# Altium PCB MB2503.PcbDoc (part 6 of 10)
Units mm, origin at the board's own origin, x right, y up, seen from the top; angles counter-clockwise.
Board outline 127 x 97 mm, 6 copper layers (Top Layer, Signal Layer 1, Signal Layer 2, Signal Layer 3, Signal Layer 4, Bottom Layer), stack 1.557 mm thick; 572 components, 468 nets, 2377 pads, 1704 vias.
Unrouted connection lines stored in the file: 3.
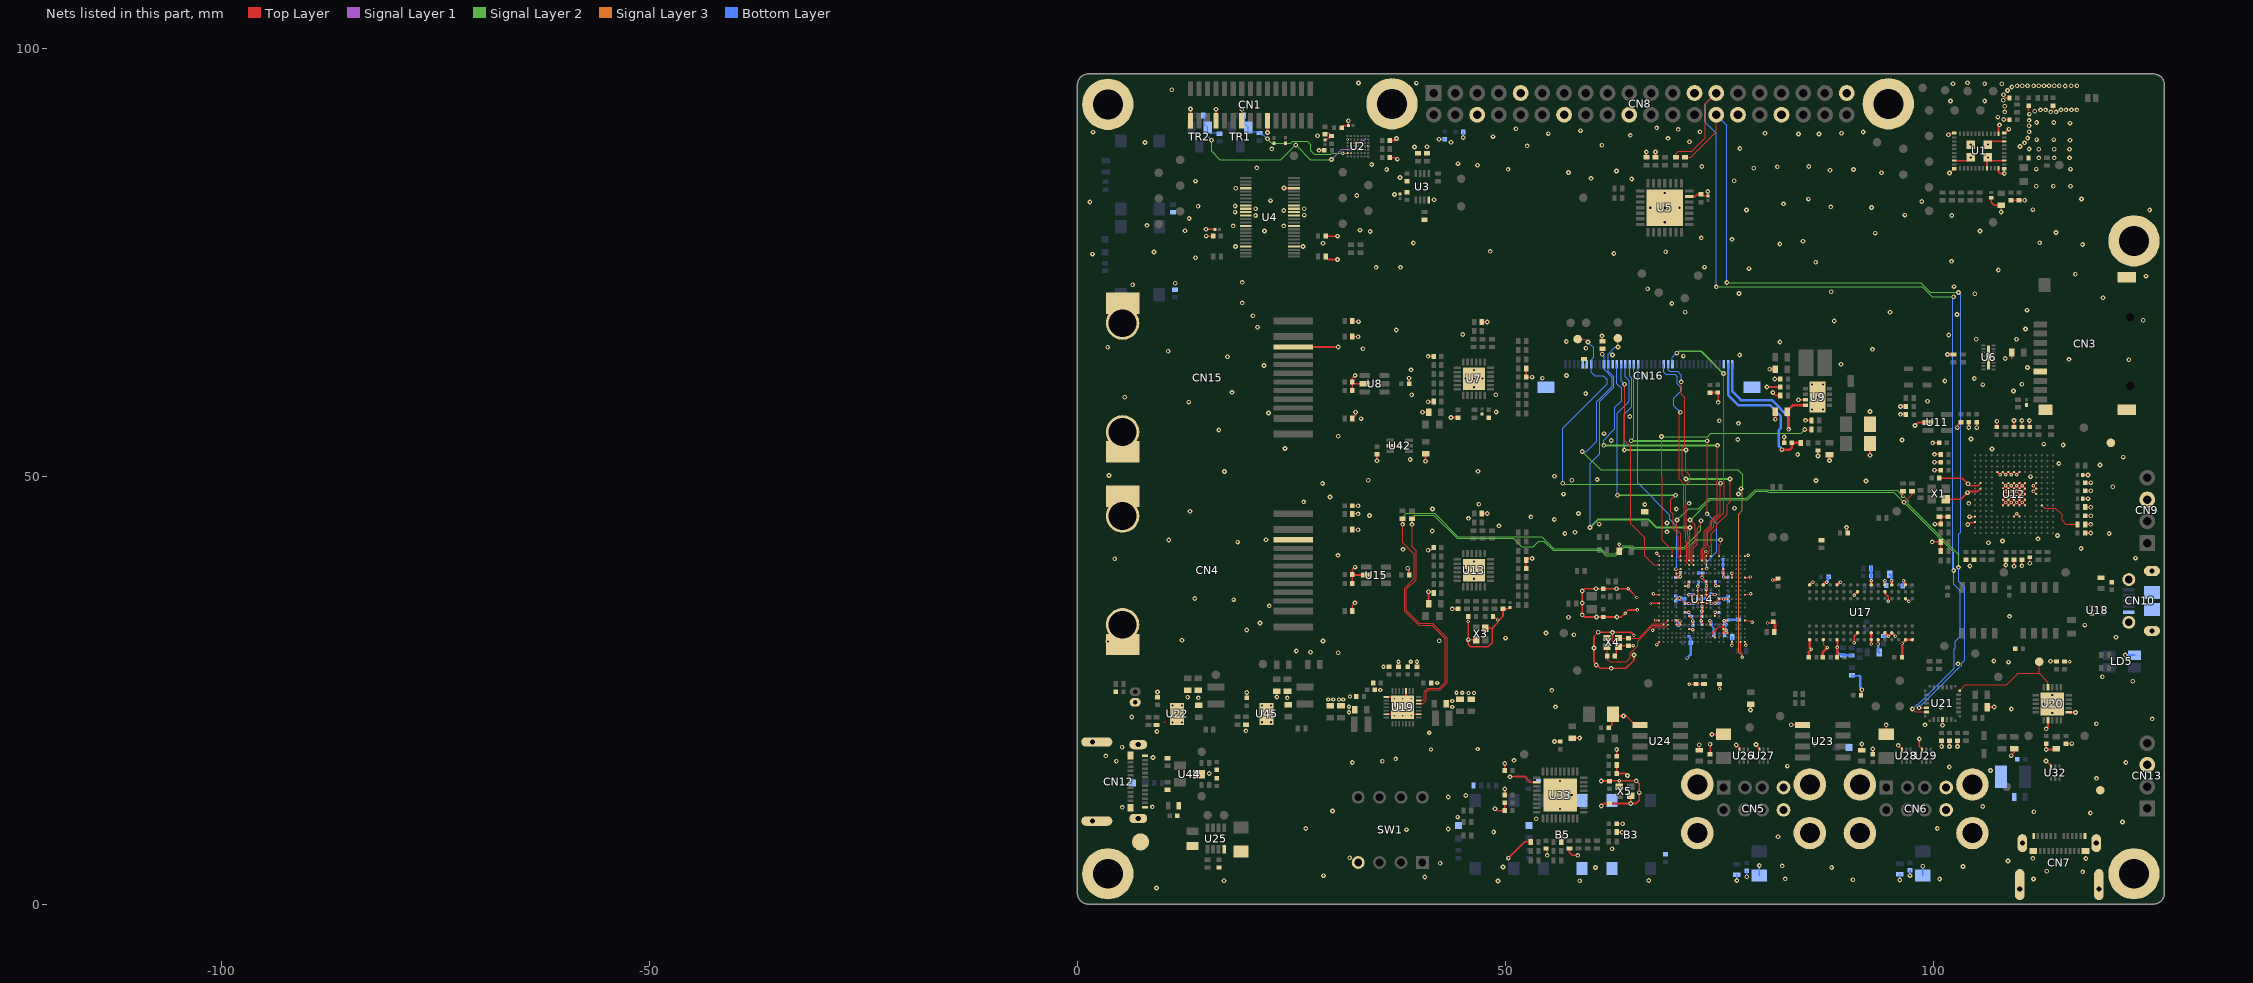
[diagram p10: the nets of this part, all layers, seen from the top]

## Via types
v1: diameter 0.55, hole 0.25, Top Layer to Bottom Layer, 1335 vias
v2: diameter 0.4, hole 0.2, Top Layer to Bottom Layer, 262 vias
v3: diameter 0.5, hole 0.2, Top Layer to Bottom Layer, 51 vias
v4: diameter 0.26, hole 0.1, Top Layer to Signal Layer 1, tented both sides, 29 vias
v5: diameter 0.5, hole 0.25, Top Layer to Bottom Layer, 18 vias
v6: diameter 0.4, hole 0.2, Top Layer to Bottom Layer, tented both sides, 9 vias

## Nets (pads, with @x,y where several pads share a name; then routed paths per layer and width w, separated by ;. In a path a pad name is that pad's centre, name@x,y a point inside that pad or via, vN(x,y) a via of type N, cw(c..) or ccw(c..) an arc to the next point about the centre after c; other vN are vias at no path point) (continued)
GND: B3.1 B3.2 B5.3 B5.4 C1.1 C2.1 C3.1 C4.1 C5.1 C6.1 C7.2 C8.1 C9.1 C10.1 C11.1 C12.1 C13.1 C14.1 C15.1 C16.1 C17.1 C18.1 C19.1 C20.1 C21.1 C22.1 C23.1 C24.1 C25.1 C26.1 C27.1 C28.1 C29.2 C30.1 C31.1 C32.1 C33.2 C34.1 C35.1 C36.2 C37.1 C38.1 C39.2 C40.1 C41.1 C42.1 C43.1 C44.1 C45.1 C46.1 C47.1 C48.1 C49.1 C50.2 C51.1 C52.1 C53.1 C54.1 C55.1 C56.1 C57.1 C58.1 C59.1 C60.1 C61.1 C62.1 C63.1 C64.1 C65.1 C66.1 C67.1 C68.1 C69.1 C70.1 C71.1 C72.1 C73.1 C74.1 C75.1 C76.1 C77.1 C78.1 C79.1 C80.1 C81.2 C82.1 C83.1 C84.1 C85.1 C88.2 C89.1 C90.1 C91.2 C92.1 C93.2 C94.1 C95.1 C96.1 C97.1 C98.1 C99.1 C100.1 C101.1 C102.1 C103.2 C104.1 C105.1 C106.1 C107.2 C108.1 C109.1 C110.1 C111.1 C112.1 C113.1 C114.1 C115.1 C116.1 C117.1 C118.2 C119.1 C120.1 C121.1 C122.1 C123.1 C124.1 C125.1 C126.1 C127.1 C128.1 C129.1 C130.1 C131.1 C133.1 C134.1 C135.1 C136.1 C137.1 C138.1 C139.1 C140.1 C142.1 C144.1 C147.1 C148.1 C149.1 C150.1 C151.2 C152.1 C153.1 C154.1 C155.1 C156.1 C157.1 C158.1 C159.1 C160.1 C161.1 C162.2 C163.1 C164.1 C165.1 C166.1 C167.1 C168.1 C169.1 C170.1 C171.1 C172.1 C173.1 C174.1 C175.1 C176.1 C177.2 C178.1 C179.1 C180.2 C181.1 C182.1 C183.1 C184.1 C185.2 C186.1 C187.1 C188.1 C189.1 C190.1 C191.2 C192.1 C193.1 C194.1 C195.2 C196.1 C197.1 C198.1 C199.1 C200.1 C201.1 C202.1 C203.2 C204.2 C205.1 C206.1 C207.2 C208.1 C209.1 C210.2 C211.1 C212.1 C213.1 C214.2 C215.2 C216.2 C217.2 C218.1 C219.2 C220.1 C221.1 C222.1 C223.1 C224.1 C225.1 C226.1 C227.1 C228.1 C229.1 CN1.1 CN1.4 CN1.7 CN1.10 CN3.6 CN3.10 CN3.11 CN3.12 CN4.10 CN4.13 CN4.14 CN5.B4 CN5.CH1 CN5.CH2 CN5.CH3 CN5.CH4 CN5.T4 CN6.B4 CN6.CH1 CN6.CH2 CN6.CH3 CN6.CH4 CN6.T4 CN7.A1 CN7.A12 CN7.B1 CN7.B12 CN7.SH1 CN7.SH2 CN7.SH3 CN7.SH4 CN8.6 CN8.9 CN8.14 CN8.20 CN8.25 CN8.30 CN8.34 CN8.39 CN9.3 CN10.5 CN10.6 CN10.7 CN10.8 CN10.9 CN10.10 CN10.11 CN11.2 CN12.A1 CN12.A12 CN12.B1 CN12.B12 CN12.SH1 CN12.SH2 CN12.SH3 CN12.SH4 CN13.3 CN15.10 CN15.13 CN15.14 CN16.3 CN16.29 CN16.35 CN16.36 CN16.MT1 CN16.MT2 LD1.2 LD2.2 LD5.4 LD6.2 LD7.2 pad.1 R3.2 R4.2 R7.1 R8.1 R13.1 R23.2 R24.1 R25.2 R27.1 R33.1 R38.2 R44.1 R47.2 R49.1 R52.1 R53.1 R58.2 R59.1 R66.1 R68.2 R69.2 R70.1 R74.1 R76.1 R84.1 R87.1 R93.2 R101.2 R110.1 R112.1 R114.1 R128.2 R134.1 R136.1 R143.1 R145.1 R146.1 R147.1 R156.1 R158.1 R159.1 R160.1 R173.2 R175.2 R176.1 R178.1 R179.1 R182.2 R200.1 R209.1 R215.1 SW1.4 TP39.1 TP75.1 TP76.1 U1.1 U1.12 U1.19 U1.21 U1.29 U1.32 U1.33 U1.35 U1.40 U1.42 U1.43 U1.44 U1.45 U1.46 U2.A4 U2.A7 U2.C5 U2.D3 U2.D5 U2.E3 U2.F6 U2.G2 U3.4 U4.4 U4.9 U4.10 U4.11 U4.12 U4.15 U4.21 U4.28 U4.34 U4.37 U4.38 U4.39 U4.40 U4.45 U5.6 U5.29 U6.EP U7.EP U8.2 U9.3 U9.9 U10.2 U11.2 U12.D5 U12.D6 U12.D7 U12.D8 U12.D9 U12.F2 U12.F6 U12.F7 U12.F8 U12.F9 U12.F10 U12.F12 U12.G2 U12.G6 U12.G7 U12.G8 U12.G9 U12.G10 U12.G12 U12.H6 U12.H7 U12.H8 U12.H9 U12.H10 U12.H12 U12.J6 U12.J7 U12.J8 U12.J9 U12.J10 U12.K6 U12.K7 U12.K8 U12.K9 U12.K10 U12.M1 U12.M8 U12.M9 U12.N1 U13.EP U14.A1 U14.A21 U14.AA1 U14.AA18 U14.AA21 U14.B12 U14.D16 U14.E5 U14.E6 U14.E11 U14.E16 U14.F5 U14.F17 U14.F18 U14.F21 U14.G8 U14.G12 U14.G14 U14.H7 U14.H15 U14.J10 U14.J12 U14.K1 U14.K9 U14.K10 U14.K11 U14.K12 U14.K13 U14.K21 U14.L5 U14.L10 U14.L12 U14.L15 U14.L17 U14.M1 U14.M7 U14.M9 U14.M10 U14.M11 U14.M12 U14.M13 U14.N11 U14.P7 U14.P15 U14.R8 U14.R11 U14.R14 U14.T1 U14.T5 U14.T17 U14.T21 U14.U3 U14.U5 U14.U6 U14.U9 U14.U11 U14.U13 U14.U16 U14.V8 U14.V16 U14.W16 U14.W17 U14.Y14 U15.2 U16.2 U17.A9 U17.B1 U17.B3 U17.B9 U17.D1 U17.D8 U17.E1 U17.E2 U17.E8 U17.F9 U17.G1 U17.G8 U17.G9 U17.J2 U17.J8 U17.M1 U17.M9 U17.P1 U17.P9 U17.T1 U17.T9 U18.3 U19.9 U19.17 U19.22 U19.27 U19.29 U20.12 U20.16 U20.21 U21.4 U22.4 U22.8 U22.9 U23.1 U24.1 U25.4 U26.3 U27.3 U28.3 U29.3 U30.2 U31.2 U32.3 U33.11 U33.37 U34.2 U36.2 U37.2 U38.2 U39.2 U40.2 U41.2 U42.2 U44.3 U45.4 U45.8 U45.9 X1.2 X3.2 X3.4 X4.2 X4.4 X5.2 X5.4 | length 403.1
  Top Layer w0.075: v2(67.2,32) 67.597,32.397 68.077,32.397 68.373,32.397 68.722,32.397 U14.U3@68.975,32.65 ; v2(73.425,41.2) 73.228,41.003 73.228,40.522 73.452,40.298 73.452,40.173 U14.B12@73.469,40.156 ; U14.Y14@74.475,31.15 74.464,31.161 74.464,31.312 74.228,31.548 74.228,31.803 74.328,31.903 74.576,31.903 74.722,32.049 74.722,32.189 74.933,32.4 75.475,32.4
  Top Layer w0.09: U14.T21@77.974,33.15 78.156,33.15 78.216,33.09 78.617,33.09 78.757,32.95 v2(78.825,32.95) ; C94.1@81.15,32.85 C94.1@81.3,33 ; U17.P9@87.15,30.9 87.209,30.84 87.209,30.703 87.22,30.692 87.22,30.33 v2(87.6,29.95)
  Top Layer w0.1: U14.K21@77.974,36.15 77.98,36.145 78.035,36.2 78.491,36.2 78.566,36.275 v2(78.65,36.275)
  Top Layer w0.12: U17.T1@85.47,37.37 U17.T1@85.545,37.295 ; U17.M1@88.745,37.295 U17.M1@88.745,37.395 ; v2@92.745,30.305 v2(92.745,30.395) ; U17.E8@94.345,31.695 U17.E8@94.365,31.695
  Top Layer w0.15: v2(72.975,38.175) 72.975,38.074 U14.G12@73.393,37.656 ; U14.AA21@77.974,30.65 78.075,30.55 v2(78.075,30.225) ; U14.F21@77.975,38.15 78.482,38.15 78.557,38.225 v2(78.625,38.225) ; v2@90.75,30.525 90.75,31.3
  Top Layer w0.175: v2@74.475,33.989 v2@74.636,34.15 ; U14.A21@77.953,40.652 77.992,40.652 78.068,40.729 78.354,40.729 v2(78.375,40.75)
  Top Layer w0.2: U22.4@10.175,21.25 10.185,21.24 ; CN1.1@13.2,91.525 v1(13.2,92.9) ; v1(15.025,78.85) C24.1@16.05,78.85 ; v1(15.05,78.05) C25.1@15.85,78.05 ; CN1.4@16.2,91.5 CN1.4@16.2,91.525 v1(16.2,92.875) ; CN1.7@19.2,91.5 CN1.7@19.2,91.525 v1(19.2,92.875) ; v1(22.2,90.15) CN1.10@22.2,91.5 ; CN15.10@25.2,65.1 v1(30.475,65.1) ; v1(28.225,88.075) C12.1@28.85,88.075 ; C117.1@28.925,89.95 29.062,90.087 29.388,90.087 29.7,89.775 29.52,89.595 29.423,89.595 29.403,89.575 29.384,89.575 29.179,89.37 29.025,89.37 C10.1@28.95,89.295 ; R23.2@29,75.65 29.325,75.325 v1(30.375,75.325) ; C26.1@29,78.05 29.004,78.054 v1(30.376,78.054) ; C6.1@30.875,90.825 31,90.95 C5.1@31.65,90.95 v1(31.65,91.525) ; R110.1@32.125,34.25 32.125,34.9 v1(32.425,35.2) ; C85.1@32.125,37.475 32.125,38.4 C80.1@32.175,38.45 ; R76.1@32.125,43.75 v1(32.8,43.75) ; R70.1@32.125,45.6 v1(32.8,45.6) ; C229.1@32.125,46.55 v1(32.8,46.55) ; R52.1@32.125,56.75 32.5,57.125 v1(32.5,57.475) ; C35.1@32.125,60 C32.1@32.125,61 ; R27.1@32.125,66.3 v1(32.8,66.3) ; R24.1@32.125,68.15 32.185,68.09 32.81,68.09 v1(32.838,68.062) ; v4(32.375,88.95) U2.D3@32.775,88.95 ; v1(32.45,39.375) 32.125,39.05 C80.1@32.125,38.5 C80.1@32.175,38.45 ; v1(32.45,61.775) 32.125,61.45 C32.1@32.125,61 ; U2.D5@32.775,88.15 v4(33.175,88.15) ; U8.2@33.575,60.8 32.325,60.8 C32.1@32.125,61 ; U15.2@33.75,38.45 C80.1@32.175,38.45 ; U19.27@36.1,22.2 37.2,22.2 v3(38,23) ; U19.22@36.1,24.2 36.8,24.2 v3(38,23) ; C14.1@36.5,87.225 37.105,87.225 37.28,87.05 v1(37.375,87.05) ; C11.1@36.5,89.225 37.05,89.225 v1(37.275,89.45) ; v3(38,24) 38.15,24 38.4,24.25 38.4,24.875 U19.17@38.4,24.9 ; v1(38.6,39.25) 38.75,39.1 C81.2@38.75,38.45 ; C33.2@38.75,60.8 v1(38.75,61.45) ; v3(39,24) v3(38,23) ; U19.9@39.9,22.2 38.8,22.2 v3(38,23) ; v1(40.325,57.475) C39.2@41.05,57.475 ; v1(40.975,41.35) 41.3,41.35 C71.1@41.625,41.675 ; v1(40.975,58.7) R47.2@41.625,58.7 ; v1(40.975,64) C28.1@41.625,64 ; C91.2@41.05,35.1 41.125,35.175 41.025,35.275 v1(41.025,36.5) 41.45,36.5 R101.2@41.625,36.325 ; v1(43.65,56.85) C37.1@44.45,56.85 ; v1(43.8,34.5) C89.1@44.45,34.5 ; C95.1@45.675,33.6 v2(45.675,33.025) v1@45.675,30.9 ; v1(45.677,30.902) v1@45.675,30.9 ; X3.4@46.575,30.9 v1@45.675,30.9 ; R69.2@47.25,45.65 v1(47.875,45.65) ; R25.2@47.25,68.025 v1(47.875,68.025) ; X3.2@47.625,32.25 48.45,32.25 ; C96.1@48.55,33.6 48.7,33.6 v2(49.1,33.2) ; v1(48.8,11.15) 49.025,10.925 C168.1@49.925,10.925 C165.1@49.925,11.85 ; C163.1@49.925,12.75 v1(49.925,13.45) ; C157.1@49.925,15.6 v1(49.925,16.425) ; v1(50.35,5.375) 52.25,7.275 R158.1@52.975,7.275 ; C92.1@50.525,34.675 50.35,34.5 C90.1@49.725,34.5 49.725,33.625 49.3,33.2 v2(49.1,33.2) ; v1(50.55,14.873) 51.059,14.925 52.25,14.925 52.925,14.25 U33.11@53.65,14.25 ; C79.1@52.425,39.2 R93.2@52.425,40.2 52.6,40.375 v1(53.125,40.375) ; R38.2@52.425,62.575 C30.1@52.425,61.575 v1(53.125,61.575) ; C170.1@54.75,6.5 54.9,6.35 v1(54.9,5.7) ; v1(55.75,19) C150.1@56.4,19 ; R159.1@56.525,7.275 v1(56.525,8) ; R160.1@57.475,6.5 57.475,6.05 57.825,5.7 v1(58.45,5.7) ; C133.1@57.8,19.4 v1(58.675,19.4) ; v1(60.625,27.95) 60.7,27.95 61.1,27.55 v1(62.375,27.55) 64.081,27.55 65.025,28.494 v1(65.025,29.1) ; v1@60.646,27.971 60.35,28.268 v1(60.35,29.925) 60.35,30.02 60.35,31.275 v1(60.85,31.775) 62.525,31.775 62.528,31.772 v1(62.528,31.752) ; v1(61.2,11.475) 61.475,11.75 C164.1@62.15,11.75 v1(64.65,11.75) ; v1(61.2,14.375) C159.1@62.15,14.375 62.175,14.4 v2(63.3,14.4) ; v1(61.3,66.4) 61.3,65.85 61.35,65.8 R59.1@61.325,65.775 ; C135.1@62.075,20.6 62.45,20.975 62.45,22.05 C130.1@62.575,22.175 62.775,21.975 v1(63.8,21.975) 64.15,21.975 65.195,20.93 U24.1@65.725,20.93 ; C103.2@62.8,29 62.95,29.15 62.95,29.825 X4.2@63.2,30.075 ; R156.1@63,8.4 v1(63.625,8.4) ; C169.1@63,9.4 v1(63.7,9.4) ; R146.1@63,16.275 C158.1@63,15.275 64.025,15.275 v1(64.275,15.025) ; C154.1@63,17.275 v1(63,18.075) ; X5.2@63.3,13.7 v2(63.3,14.4) ; C72.1@63.3,41.25 v2@63.3,41.975 ; X5.4@64.65,12.65 v1(64.65,11.75) ; v2(64.95,30.175) C98.1@64.375,30.175 63.3,30.175 X4.2@63.2,30.075 ; v2(65.025,31.425) 64.7,31.75 64.65,31.7 64.598,31.752 v1(62.528,31.752) ; v2(65.375,35.825) v2(64.35,36.85) v1(62.975,36.85) C88.2@61.425,36.85 v1(60.6,36.85) 59.25,36.85 v1(58.975,36.575) v1(58.975,35.188) v1(58.975,33.8) 59.225,33.55 v1(60.65,33.55) C93.2@61.425,33.55 v1(63.025,33.55) 63.55,33.55 v2(64,34) 64.375,34.375 v2(65.4,34.375) ; R7.1@66.475,87.25 v1(66.475,87.875) ; v4@66.975,35.15 U14.M1@67.975,35.15 ; v2(67.3,36.25) 67.4,36.15 U14.K1@67.975,36.15 ; R8.1@67.55,87.25 v1(67.55,87.875) ; v4@67.558,33.15 U14.T1@67.975,33.15 ; U14.L5@69.975,35.65 69.981,35.656 70.177,35.656 70.296,35.775 v2(70.35,35.775) 70.65,35.475 70.666,35.475 70.9,35.241 70.9,35.233 70.975,35.158 U14.M7@70.975,35.15 71.425,35.15 v2(71.45,35.125) 71.475,35.15 U14.M10@72.475,35.15 ; v2@70.425,38.275 70.431,38.269 v2@70.436,38.269 ; U14.E6@70.475,38.65 U14.E6@70.475,38.644 ; U14.P7@70.975,34.15 71.296,34.15 71.346,34.1 v2@71.438,34.1 ; U14.H7@70.975,37.15 70.977,37.152 71.373,37.152 v2(71.375,37.15) 71.375,37.204 71.329,37.251 71.329,37.504 U14.G8@71.475,37.65 ; v2@71.419,34.081 v2@71.438,34.1 ; v2(71.45,34.1) v2@71.438,34.1 ; v2@71.451,36.15 U14.K10@72.475,36.15 ; v2(71.475,25.7) 73.2,25.7 R128.2@73.225,25.725 ; U14.V8@71.475,32.15 71.825,32.15 v2@71.9,32.075 ; v2@71.475,33.971 U14.R8@71.475,33.65 71.862,33.263 71.862,33.113 v2(71.9,33.075) 71.9,32.733 71.975,32.658 U14.U9@71.975,32.65 ; U5.6@71.475,82.675 72.175,82.675 72.425,82.925 C22.1@72.85,82.925 73,82.775 73.625,82.775 C23.1@73.65,82.75 v1(73.65,83.275) ; U14.L10@72.475,35.617 U14.M10@72.475,35.15 ; U14.L10@72.475,35.683 U14.K10@72.475,36.15 ; v2(72.475,37.125) U14.K10@72.475,36.15 ; U30.2@72.65,17.975 v1(72.65,18.625) ; v2(72.9,33.1) 72.9,33.567 72.975,33.642 v2@72.975,34.225 ; v2(72.95,34.225) v2@72.975,34.225 ; U14.U11@72.975,32.65 v2@72.975,33.1 ; v2(72.975,38.175) U14.E11@72.975,38.65 ; U14.G12@73.393,37.656 73.469,37.656 U14.G12@73.475,37.65 v2@73.475,37.199 ; v2@73.476,37.2 v2(73.5,37.2) 73.5,37.176 73.48,37.156 73.48,36.655 73.475,36.65 U14.K12@73.475,36.15 ; v2(73.9,33.1) 73.975,33.1 U14.U13@73.975,32.65 ; C50.2@73.905,59.775 74.83,59.775 74.875,59.73 v1(74.875,58.625) ; C152.1@73.925,17.5 v1(73.925,18.675) ; v1(74.125,19.825) C136.1@75.323,19.825 ; U14.R14@74.475,33.65 v2@74.475,33.989 ; U14.G14@74.475,37.65 74.481,37.644 U14.G14@74.481,37.623 ; U14.G14@74.481,37.623 74.481,37.373 74.575,37.279 v2(74.575,37.225) 74.604,37.225 74.654,37.275 74.773,37.156 74.969,37.156 U14.H15@74.975,37.15 ; v2(74.5,36.175) 74.475,36.15 U14.K12@73.475,36.15 ; v2@74.636,34.15 U14.P15@74.975,34.15 ; v2(75.025,25.175) C119.1@75.025,25.725 ; C136.1@75.324,19.826 75.4,19.75 C136.1@75.5,19.85 ; U14.V16@75.45,32.125 75.474,32.101 U14.W16@75.474,31.65 ; U14.V16@75.474,32.15 75.48,32.144 75.686,32.144 v2@75.804,32.027 ; U14.W16@75.474,31.65 75.974,31.65 75.969,31.656 75.969,31.704 75.912,31.761 75.912,31.918 v2@75.804,32.027 ; U14.V16@75.475,32.175 75.475,32.4 75.475,32.971 75.575,33.071 v2(75.575,33.125) ; U14.D16@75.475,39.15 75.475,38.329 75.525,38.279 v2(75.525,38.225) 75.579,38.225 75.654,38.15 U14.F17@75.975,38.15 ; v2@75.538,33.125 75.519,33.144 75.969,33.144 U14.T17@75.975,33.15 ; v2(75.804,32.002) v2@75.804,32.027 ; U14.L17@75.974,35.65 v2(75.525,35.65) U14.L15@74.975,35.65 74.969,35.644 74.969,35.604 74.515,35.15 v2(74.5,35.15) U14.M12@73.475,35.15 ; v2(76.475,30.225) U14.AA18@76.475,30.65 ; U14.F18@76.475,38.15 v2(76.475,38.65) ; v1(76.979,18.601) 77.024,18.601 77.35,18.275 U26.3@77.35,18 ; v1(78.65,22.675) C124.1@78.65,23.35 ; v1(79.275,18.65) 79.675,18.25 U27.3@79.675,18 ; v1(80.55,60.425) C34.1@82.125,60.425 ; v1(80.875,62.5) C29.2@81.55,62.5 ; v1(81.254,59.778) 81.254,59.746 81.575,59.425 R44.1@82.125,59.425 ; v1(81.475,61.35) C31.1@82.125,61.35 ; v1(81.55,56.65) R49.1@81.55,57.525 ; C54.1@82.575,53.9 v1(82.575,54.575) ; v1(83.395,20.955) U23.1@84.725,20.955 ; v1(84.25,58.925) U9.3@85.075,58.925 ; v1(85.075,56.525) R53.1@85.775,56.525 ; v1(86.525,52.35) C56.1@86.525,53 ; v1(87.875,51.825) C52.1@87.875,52.5 ; C121.1@91.55,24.395 91.6,24.445 91.6,25 v1(91.65,25.05) ; U31.2@91.65,17.975 v1@91.65,18.65 ; v1(92.6,52.45) C51.1@92.6,53.825 ; C153.1@92.925,17.5 v1(92.925,18.125) ; U17.E2@94.35,36.5 94.388,36.461 94.388,36.254 94.744,35.899 ; C137.1@94.5,19.85 v1(94.5,20.95) ; v2@94.744,35.381 v2(94.75,35.375) ; v2@94.75,35.381 94.75,35.899 ; v1(95.9,18.55) 96.35,18.1 U28.3@96.35,18 ; v1(96.175,57.225) C41.1@96.8,57.225 ; v1(96.175,58.15) C36.2@96.8,58.15 ; U17.B3@96.78,35.67 97.075,35.375 v2(97.15,35.375) ; v1(97.85,55.925) 98.2,56.275 U11.2@99.375,56.275 ; v1(98.375,19.3) 98.375,18.425 98.675,18.125 U29.3@98.675,18 ; v1(99.875,42.325) R84.1@100.875,42.325 R87.1@100.875,41.25 ; v1(99.925,53.9) C55.1@100.675,53.9 ; v1(100.15,50.7) C59.1@100.875,50.7 ; v1(100.15,51.625) C58.1@100.875,51.625 ; v1(100.15,52.55) C57.1@100.875,52.55 ; v1(100.2,44.4) C68.1@100.875,44.4 100.875,45.125 R68.2@100.725,45.275 C65.1@101.725,45.275 ; C61.1@100.7,49.775 103.4,49.775 v1(104.05,49.125) 104.3,48.875 105.2,48.875 U12.F2@105.525,49.2 ; v1(100.975,18.425) C138.1@100.975,19.1 ; v1(101.075,20.9) U21.4@101.075,21.575 ; X1.2@101.45,47.3 103.225,47.3 104.15,48.225 105.2,48.225 U12.G2@105.525,48.55 ; v1@101.7,64.225 R33.1@102.375,64.225 ; v1(101.775,89.9) 101.962,90.087 U1.12@102.45,90.087 ; v1(101.9,18.425) C139.1@101.9,19.1 ; v1(101.9,85.425) 101.925,85.425 102.413,85.913 U1.21@102.45,85.913 ; U1.19@102.45,86.875 104,86.875 v1(104.375,87.25) ; v1(102.8,55.675) 102.8,55.9 C42.1@103.225,56.325 ; v1(102.825,18.425) C140.1@102.825,19.1 ; v1(104.025,44.35) 104.092,44.35 104.317,44.575 104.786,44.575 104.861,44.65 U12.N1@104.875,44.65 ; v1(104.15,55.7) C43.1@104.15,56.325 ; v1(104.225,45.275) 104.85,45.275 U12.M1@104.875,45.3 ; v1(105.075,55.675) C44.1@105.075,56.325 ; U1.29@106.275,85.975 106.275,87.15 v1(106.375,87.25) 106.75,86.875 U1.35@108.3,86.875 ; R134.1@106.325,23.025 v1(107.125,23.025) ; v1(106.375,88.75) 106.775,89.15 107.378,89.15 107.772,89.15 108.275,89.15 U1.40@108.3,89.125 ; C18.1@106.775,82.55 106.775,82.025 107.125,81.675 C19.1@107.925,81.675 107.925,81.175 ; C46.1@107.425,55.75 v1(107.425,56.425) ; U12.D5@107.475,50.5 v2(107.8,50.175) U12.D6@108.125,50.5 v2(108.45,50.175) U12.D7@108.775,50.5 v2(109.1,50.175) U12.D8@109.425,50.5 v2(109.75,50.175) U12.D9@110.075,50.5 ; U1.32@107.625,85.975 107.625,85.525 107.775,85.375 v1(108.3,85.375) U1.33@108.3,85.913 ; U1.1@107.625,90.025 107.625,90.95 v1(107.725,91.05) ; U12.K6@108.125,46.6 v2(108.45,46.925) ; U12.F6@108.125,49.2 v2(108.45,48.875) ; U1.42@108.3,90.087 108.362,90.087 v1(108.825,90.55) ; 108.425,94.2 C1.1@108.9,94.2 ; v1(108.475,39.625) 108.475,40.225 C76.1@108.5,40.25 ; v1@108.475,91.65 C4.1@108.9,91.65 ; C20.1@109.075,82.25 C21.1@110,82.25 v1(110.675,82.25) ; v1(109.1,17.35) 109.422,17.672 109.422,18.122 R143.1@109.475,18.175 ; 109.175,63.725 C27.1@109.175,64.45 ; v1(109.425,39.475) C77.1@109.425,40.25 ; U12.M8@109.425,45.3 v2(109.75,45.625) U12.M9@110.075,45.3 ; C47.1@109.425,55.75 v1(109.425,56.5) ; v1(110.35,39.525) C78.1@110.35,40.25 ; C48.1@110.35,55.75 v1(110.35,56.5) ; U12.K10@110.725,46.6 v2(110.4,46.925) ; U12.F10@110.725,49.2 v2(110.4,48.875) ; 111.125,92.775 111.125,93.275 C2.1@111.15,93.3 ; v1(111.225,56.5) 111.225,55.8 C49.1@111.275,55.75 ; v1(111.275,39.825) C73.1@111.275,40.55 ; U12.H12@112.025,47.9 v2(111.7,48.225) U12.G12@112.025,48.55 v2(111.7,48.875) U12.F12@112.025,49.2 ; v1(113.175,16.725) 113.75,16.15 U32.3@113.75,16 ; C147.1@113.2,18.75 v1(113.2,18.075) 114.25,18.075 C149.1@114.35,18.175 ; v1(113.2,20.475) 113.4,20.675 U20.12@113.4,21.475 ; v1(113.7,28.375) 114.375,28.375 C108.1@114.4,28.35 ; 114,92.9 C3.1@114,93.3 ; C109.1@115.325,28.35 115.35,28.325 v2(115.925,28.325) ; C148.1@115.5,18.75 v1(116.175,18.75) ; U20.16@115.825,22.4 v1(116.625,22.4) ; C64.1@117.45,47.375 v1(118.075,47.375) ; C60.1@117.45,50.15 v1(118.075,50.15) ; C69.1@117.75,43.375 v1(118.4,43.375) ; R74.1@117.75,44.375 v1(118.4,44.375) ; C67.1@117.75,45.375 v1(118.4,45.375) ; R66.1@117.75,46.375 v1(118.4,46.375) ; C63.1@117.75,48.3 v1(118.4,48.3) ; C62.1@117.75,49.225 117.775,49.25 v1(118.4,49.25) ; v1@45.675,30.9 45.675,30.375 45.975,30.075 47.975,30.075 48.45,30.55 48.45,32.25 ; 48.45,32.25 49.1,32.9 v2(49.1,33.2) ; v1(62.528,31.752) 62.528,30.672 63.125,30.075 X4.2@63.2,30.075 ; v2(63.3,14.4) v1(65.3,14.4) 65.65,14.05 v1(65.65,13.025) 65.65,12.125 65.275,11.75 v1(64.65,11.75) ; v2@70.436,38.269 v2(70.436,38.274) 70.436,38.318 70.425,38.329 70.475,38.379 U14.E6@70.475,38.644 ; v2@70.436,38.269 70.342,38.175 70,38.175 U14.F5@69.975,38.15 U14.E5@69.975,38.65 69.981,38.644 U14.E6@70.475,38.644 ; U14.M10@72.475,35.15 U14.M11@72.975,35.15 ; U14.K10@72.475,36.15 U14.K11@72.975,36.15 ; v2@72.975,34.225 U14.M11@72.975,35.15 ; U14.M11@72.975,35.15 U14.M12@73.475,35.15 ; U14.M11@72.975,35.15 v2(72.975,35.65) U14.K11@72.975,36.15 ; U14.K11@72.975,36.15 U14.K12@73.475,36.15 ; U14.M12@73.475,35.15 U14.K12@73.475,36.15 ; v2(108.45,46.925) U12.K7@108.775,46.6 v2(109.1,46.925) ; v2(108.45,46.925) U12.J6@108.125,47.25 v2(108.45,47.575) ; v2(108.45,46.925) U12.J7@108.775,47.25 ; v2(108.45,47.575) U12.H7@108.775,47.9 ; v2(108.45,47.575) U12.H6@108.125,47.9 v2(108.45,48.225) ; v2(108.45,47.575) U12.J7@108.775,47.25 ; v2(108.45,48.225) U12.H7@108.775,47.9 ; v2(108.45,48.225) U12.G6@108.125,48.55 v2(108.45,48.875) ; v2(108.45,48.225) U12.G7@108.775,48.55 ; v2(108.45,48.875) U12.F7@108.775,49.2 v2(109.1,48.875) ; v2(108.45,48.875) U12.G7@108.775,48.55 ; U12.J7@108.775,47.25 v2(109.1,47.575) ; U12.J7@108.775,47.25 v2(109.1,46.925) ; U12.H7@108.775,47.9 v2(109.1,47.575) ; U12.H7@108.775,47.9 v2(109.1,48.225) ; U12.G7@108.775,48.55 v2(109.1,48.225) ; U12.G7@108.775,48.55 v2(109.1,48.875) ; v2(109.1,46.925) U12.K8@109.425,46.6 v2(109.75,46.925) ; v2(109.1,46.925) U12.J8@109.425,47.25 ; v2(109.1,47.575) U12.J8@109.425,47.25 ; v2(109.1,47.575) U12.H8@109.425,47.9 ; v2(109.1,48.225) U12.G8@109.425,48.55 ; v2(109.1,48.225) U12.H8@109.425,47.9 ; v2(109.1,48.875) U12.G8@109.425,48.55 ; v2(109.1,48.875) U12.F8@109.425,49.2 v2(109.75,48.875) ; U12.J8@109.425,47.25 v2(109.75,47.575) ; U12.J8@109.425,47.25 v2(109.75,46.925) ; U12.H8@109.425,47.9 v2(109.75,47.575) ; U12.H8@109.425,47.9 v2(109.75,48.225) ; U12.G8@109.425,48.55 v2(109.75,48.875) ; U12.G8@109.425,48.55 v2(109.75,48.225) ; v2(109.75,46.925) U12.K9@110.075,46.6 v2(110.4,46.925) ; v2(109.75,46.925) U12.J9@110.075,47.25 ; v2(109.75,47.575) U12.J9@110.075,47.25 ; v2(109.75,47.575) U12.H9@110.075,47.9 ; v2(109.75,48.225) U12.H9@110.075,47.9 ; v2(109.75,48.225) U12.G9@110.075,48.55 ; v2(109.75,48.875) U12.G9@110.075,48.55 ; v2(109.75,48.875) U12.F9@110.075,49.2 v2(110.4,48.875) ; U12.J9@110.075,47.25 v2(110.4,46.925) ; U12.J9@110.075,47.25 v2(110.4,47.575) ; U12.H9@110.075,47.9 v2(110.4,47.575) ; U12.H9@110.075,47.9 v2(110.4,48.225) ; U12.G9@110.075,48.55 v2(110.4,48.225) ; U12.G9@110.075,48.55 v2(110.4,48.875) ; v2(110.4,46.925) U12.J10@110.725,47.25 v2(110.4,47.575) ; v2(110.4,47.575) U12.H10@110.725,47.9 v2(110.4,48.225) ; v2(110.4,48.225) U12.G10@110.725,48.55 v2(110.4,48.875) ; U14.U5@69.975,32.65 U14.U6@70.475,32.65 70.475,32.658 70.496,32.679 70.496,32.925 70.4,33.021 v2(70.4,33.075) 70.346,33.075 70.271,33.15 U14.T5@69.975,33.15 U14.U5@69.975,32.65
  Top Layer w0.23: v2(67.675,30.325) 67.975,30.625 U14.AA1@67.975,30.65 ; v2(67.675,41) 67.675,40.973 67.975,40.673 U14.A1@67.975,40.65
  Top Layer w0.25: v1(24.125,83.675) 24.15,83.65 U4.45@25.3,83.65 ; v1(35,51.8) C101.1@35,52.525 ; U42.2@36.55,53.55 v1(37.65,53.55) ; v1(40.675,51.75) C115.1@40.675,52.6 ; v2(80.625,32.85) C94.1@81.15,32.85 ; U17.M9@88.75,30.9 88.779,30.871 88.779,30.765 88.802,30.742 88.802,30.065 88.769,30.032 v2(88.769,29.992)
  Top Layer w0.28: v2@96.544,37.794 96.544,37.754 96.575,37.723 96.575,37.578 96.731,37.422 96.731,37.319 U17.B1@96.75,37.3
  Top Layer w0.3: v2(81.25,37.875) 81.675,37.875 C82.1@81.85,38.05 ; C94.1@81.3,33 81.5,32.8 81.5,32 R112.1@81.4,31.9 ; C105.1@85.45,28.85 85.45,29.475 v2(85.75,29.775) 85.55,29.975 U17.T9@85.55,30.9 ; U17.T1@85.55,37.3 85.831,37.581 85.931,37.581 v2@85.95,37.6 ; C106.1@87.1,28.85 87.1,29.45 v2@87.581,29.931 ; U17.P1@87.15,37.3 87.431,37.581 87.531,37.581 v2@87.55,37.6 ; U17.M1@88.745,37.295 U17.M1@88.75,37.3 89.026,37.576 89.126,37.576 v2(89.145,37.595) ; C107.2@88.769,28.869 v2@88.769,29.965 ; v1(89.85,44.025) 89.898,43.977 89.898,43.472 C70.1@90,43.37 ; 90.75,31.3 U17.J8@91.15,31.7 ; v2(90.75,36.1) U17.J2@91.145,36.495 ; v2(92.745,30.395) U17.G8@92.745,31.695 ; U17.G1@92.745,37.295 v2(92.745,37.795) ; v2(93.545,30.395) U17.F9@93.545,30.895 ; v2@94.32,37.795 94.345,37.77 U17.E1@94.345,37.295 ; U17.E8@94.345,31.695 v2(94.745,31.295) U17.D8@95.145,31.695 ; v2(95.125,37.8) 95.125,37.395 95.131,37.39 95.131,37.309 U17.D1@95.145,37.295 ; U17.D8@95.15,31.7 95.162,31.7 95.562,31.3 v6(95.575,31.3) ; C104.1@96.35,28.85 v6(96.35,30.45) 96.731,30.831 96.731,30.881 U17.B9@96.75,30.9 ; U17.B9@96.745,30.868 96.745,30.895 U17.A9@97.545,30.895
  Signal Layer 1 w0.1: v4(32.375,88.95) 32.394,88.95 32.514,89.07 33.124,89.07 33.292,89.237 33.488,89.237 33.72,89.47
  Signal Layer 1 w0.25: v2(80.625,32.85) v2@80.65,32.875
  Bottom Layer w0.1: C194.1@70.975,35.7 C194.1@71,35.675 ; v2@76.47,38.645 v2@76.527,38.702
  Bottom Layer w0.2: v1(42.25,89.375) C7.2@42.925,89.375 ; v1(45.075,89.575) C8.1@45.075,90.225 ; C201.1@71,35.15 C194.1@71,35.675 ; v2(71.45,34.1) 71.45,34.096 71.4,34.046 71.675,33.771 71.675,33.6 71.896,33.379 71.896,33.079 v2(71.9,33.075) ; C212.1@74.1,32.65 74.1,32.525 74.325,32.3 C217.2@74.325,31.475 ; C175.1@75.425,38.725 C173.1@75.425,39.7 C171.1@75.425,40.275 ; C216.2@75.575,31.55 C216.2@75.625,31.5 ; C216.2@75.625,31.475 75.725,31.575 75.725,31.846 75.8,31.921 v2@75.8,31.95 ; C211.1@75.75,32.65 75.75,32.075 v2@75.8,32.025 ; v2(76.475,30.225) 76.475,31.2 R200.1@76.5,31.225 ; v1(77.05,2.75) U39.2@77.05,3.425 ; v1(78.2,3.2) C227.1@78.2,3.9 ; C225.1@79.675,3.35 v1(79.675,4.525) ; R209.1@90.5,26.725 90.55,26.675 91.35,26.675 ; v1(96.075,2.825) 96.075,3.394 U38.2@96.075,3.475 ; v1(97.275,3.325) C226.1@97.275,3.95 ; C224.1@98.775,3.35 v1(98.775,4.425) ; v1(122.425,29.1) LD5.4@123.525,29.1
  Bottom Layer w0.25: v2@88.739,29.935 88.739,29.524 89.083,29.18
  Bottom Layer w0.3: C207.2@69.975,33.125 70,33.1 70.373,33.1 70.398,33.075 v2(70.4,33.075) 70.4,33.073 v2@70.425,33.048 ; C191.2@69.975,35.975 70.375,35.575 v2@70.438,35.638 ; C197.1@70,35.475 70.08,35.555 70.43,35.555 70.475,35.6 v2@70.438,35.638 ; C183.1@70,38.2 70.025,38.225 70.348,38.225 70.398,38.275 70.404,38.269 70.436,38.269 v2(70.436,38.274) 70.436,38.291 70.425,38.302 70.45,38.327 70.45,38.625 C174.1@70.475,38.65 ; C215.2@70.25,32.55 70.275,32.575 70.275,32.898 v2@70.425,33.048 ; v2@70.425,33.025 v2@70.425,33.048 ; C194.1@70.975,35.7 70.85,35.575 70.65,35.775 v2@70.375,35.775 ; C205.1@71,34.05 71.025,34.075 71.348,34.075 71.373,34.1 v2(71.45,34.1) ; C201.1@71,35.15 71.013,35.138 71.438,35.138 v2(71.45,35.125) 71.463,35.113 71.888,35.113 C202.1@71.9,35.1 ; v2(71.225,28.75) 71.25,28.75 71.655,29.155 C220.1@71.655,30.545 71.655,31.02 C219.2@71.43,31.245 ; v2(71.375,37.15) 71.375,37.152 71.325,37.202 71.425,37.302 71.425,37.6 C187.1@71.45,37.625 ; v2(71.45,36.149) 71.477,36.149 71.503,36.175 71.9,36.175 C190.1@71.925,36.2 ; C214.2@71.9,32.55 71.925,32.575 71.925,33.023 71.9,33.048 v2(71.9,33.075) ; C196.1@72.475,35.65 v2(72.975,35.65) 73.025,35.7 C195.2@73.45,35.7 ; v2(72.475,37.125) 72.475,37.152 72.525,37.202 72.525,37.6 C186.1@72.55,37.625 ; C177.2@72.55,38.7 72.563,38.688 73.088,38.688 C176.1@73.1,38.675 72.994,38.569 72.994,38.194 v2(72.975,38.175) ; v2(72.9,33.1) 72.9,32.775 C213.1@73,32.675 ; v2(72.95,34.225) v2@72.95,34.15 ; C208.1@72.975,33.7 72.95,33.725 v2@72.95,34.15 ; 73,34.55 72.988,34.538 72.988,34.113 v2@72.95,34.15 ; C189.1@73.45,36.75 73.475,36.775 73.475,37.124 73.5,37.149 v2(73.5,37.2) 73.5,37.201 73.475,37.226 73.475,37.625 C185.2@73.45,37.65 ; v2(73.9,33.1) 73.975,33.1 74.025,33.05 74.025,32.75 C212.1@74.1,32.675 ; C188.1@74,36.25 74.025,36.225 74.348,36.225 74.423,36.15 74.448,36.175 v2@74.475,36.175 ; C200.1@74,35.15 v2@74.475,35.15 ; v2@74.463,36.163 v2@74.475,36.175 ; v2@74.475,35.149 74.488,35.162 74.962,35.162 C199.1@74.975,35.175 ; v2(74.5,34.1) 74.519,34.119 C204.2@74.975,34.119 ; v2(74.5,36.175) v2@74.475,36.175 ; C184.1@74.55,37.675 74.575,37.65 74.575,37.327 74.6,37.302 74.575,37.277 v2(74.575,37.225) ; C193.1@74.975,35.725 75,35.7 75.448,35.7 75.498,35.65 v2(75.525,35.65) ; C175.1@75.425,38.675 75.45,38.65 75.45,38.277 75.475,38.252 75.475,38.225 75.488,38.213 75.963,38.213 C182.1@75.975,38.2 ; v2@75.527,33.125 75.577,33.175 75.975,33.175 C206.1@76.025,33.225 ; v2(75.575,33.125) 75.575,33.098 75.7,32.973 75.7,32.675 C211.1@75.725,32.65 ; C198.1@76,35.45 75.819,35.631 75.544,35.631 v2(75.525,35.65) ; C192.1@76,36 75.669,35.669 75.544,35.669 v2(75.525,35.65) ; C206.1@76.05,33.2 76.075,33.225 77.12,33.225 77.12,33.245 C210.2@77.225,33.35 ; v2@87.55,37.6 87.55,37.627 87.67,37.747 87.67,38.145 C181.1@87.775,38.25 ; v2@88.739,29.935 88.769,29.965 v2(88.769,29.992) ; 89.083,29.18 89.37,29.18 89.475,29.075 90.4,29.075 R179.1@90.45,29.025 ; v1(89.85,44.025) v1@89.898,44.073 ; 91.35,26.675 91.46,26.565 91.46,25.307 91.602,25.165 91.602,25.102 91.6,25.1 91.602,25.098 91.765,25.098 v1@91.768,25.1 ; R215.1@92.74,39.427 92.725,39.412 R215.1@92.725,39.225 C180.2@92.725,38.375 92.735,38.365 92.735,37.805 v2(92.745,37.795) ; v2(93.545,30.395) 93.545,29.53 C112.1@93.675,29.4 ; C218.1@94.165,31.325 94.185,31.305 94.755,31.305 v2(94.745,31.295) ; v2@94.364,37.814 v2(94.345,37.795) 94.345,37.768 94.395,37.718 94.395,37.32 C179.1@94.5,37.215 ; C172.1@94.9,38.55 95.07,38.38 95.07,37.882 95.125,37.827 v2(95.125,37.8) ; C178.1@96.425,37.175 96.525,37.275 v2(96.525,37.8) ; v2@70.375,35.775 v2(70.35,35.775) 70.35,35.725 v2@70.438,35.638 ; v2@70.375,35.775 70.475,35.675 v2@70.438,35.638
  other v1: 9.225,1.875 49.15,2.7 17.125,2.725 58.675,2.725 66.75,2.75 90.6,2.85 100.745,2.933 111.7,2.925 82.7,2.95 40.575,3.175 28.75,3.325 117.45,3.775 113.25,3.85 60.525,4.275 88.125,4.275 49.725,4.35 103.475,4.4 82.352,4.473 42.375,4.775 108.725,5.05 117.825,5.325 111.625,5.35 31.8,5.425 62.475,6.475 81.85,7.875 48.625,8.425 38.45,8.7 43.325,8.775 26.675,8.825 100.475,8.825 122.1,9.6 53.6,9.975 44.425,10.163 118.35,10.65 111.75,10.8 29.8,10.875 56.4,11.1 5.233,11.308 8.75,11.367 105.775,11.4 43.325,12.525 45.375,12.7 56.4,12.75 57.75,12.75 56.4,14.4 119.075,14.7 15.4,15.275 106.675,15.62 101.875,16.025 82.95,16.125 32.125,16.55 122.5,16.55 4.55,16.7 35.625,16.7 51,16.8 37.175,16.975 8.825,17.125 3.3,17.325 5.225,18.325 86.15,18.675 91.65,18.7 9.275,20.175 19.675,20.25 99.025,20.95 119.05,21.075 11.1,21.225 12.2,21.225 21.575,21.25 22.625,21.25 125.575,21.65 6.35,21.875 11.65,22.225 22.1,22.25 113.9,22.35 109.125,22.8 100.875,23 55.85,23.05 21.575,23.2 22.625,23.2 11.1,23.225 12.2,23.225 112.85,23.4 113.9,23.4 114.95,23.4 14.125,24.1 24.525,24.1 12.875,24.175 23.3,24.2 113.9,24.45 19.775,24.725 9.35,24.775 55.425,24.975 123.3,26.05 119.75,26.575 102.875,28.075 108.775,28.275 107.075,28.4 30.475,29.375 27.225,29.425 25.575,29.575 3.575,30.675 28.7,30.75 42.275,30.775 12.225,30.825 50.025,31.075 121.35,31.175 58,31.475 54.75,31.675 19.775,32.025 117.7,32.6 21.325,32.85 57.375,33.525 108.9,33.625 22.425,34.851 18.25,35.575 13.7,35.7 46.325,38.025 45.325,39.025 46.325,39.025 47.325,39.025 104.275,39.5 46.325,40.025 4.35,40.35 123.625,40.425 30.45,40.75 38.05,41.45 117.275,41.55 106.45,42.225 18.722,42.296 108.075,42.425 10.675,42.55 22.025,42.575 112.225,42.675 114.5,43.075 56.95,43.3 120.55,43.3 58.125,43.45 68.875,43.5 41.45,43.6 49.25,44.2 60.975,44.4 68.875,44.525 55.725,44.95 45.7,45.075 52.975,45.25 34.125,45.4 58.55,45.65 13.15,45.9 41.475,46.175 69.975,46.175 76.775,46.25 66.3,46.7 46.9,46.725 71.475,46.825 104.15,46.825 26.425,47 29.501,47.577 56.8,47.9 77.25,47.925 104,48.075 120.975,48.775 28.65,49.15 92.125,49.45 86.3,49.5 33.975,49.525 57.75,49.525 60.725,49.625 111.35,49.95 55.75,50 3.675,50.075 17.175,50.55 46.8,50.575 119.475,51.3 114.675,51.475 38.875,51.95 122.2,52.225 84.15,52.525 106.85,53.175 24.25,53.225 115.175,53.65 112.9,53.75 62.375,54.175 96.35,54.225 77.15,54.3 104.4,54.35 30.475,54.675 61.525,54.975 16.525,55.4 77.25,56.175 75,56.475 33.15,56.725 64.525,56.975 22.325,57.376 48.925,57.5 92.6,57.55 85.825,57.8 87.125,57.8 13,58.65 99.325,58.75 5.525,59.225 86.475,59.25 39.05,59.525 48.875,59.525 59.375,59.675 18.05,59.8 109.375,59.95 46.325,60.4 85.825,60.7 87.125,60.7 105.775,60.7 110.35,60.75 101.35,61.125 45.325,61.4 46.325,61.4 47.325,61.4 104.8,61.425 54.325,61.45 57.15,61.775 66.225,61.8 46.325,62.4 38.975,62.425 111,62.7 21.8,62.925 89.225,63.075 122.85,63.6 115.85,63.65 108.4,63.75 17.525,63.95 70.8,64.025 62.525,64.15 77.375,64.15 101.65,64.225 10.6,64.6 92.9,64.825 33.35,64.9 59.4,64.95 3.525,65.075 82.075,65.675 57.125,65.75 105.025,66 109.725,66 101.8,66.5 45.025,66.55 37.25,67.075 110.775,67.2 21.05,67.4 88.425,68.125 124.525,68.225 20.5,68.75 102.775,68.9 71.025,69.15 94.95,69.15 110.95,69.4 69.45,70.175 19.25,70.25 119.825,70.85 104.85,71.325 77.3,71.35 88.075,71.55 66.625,71.9 102.425,72.15 6.45,72.375 11.425,72.55 19.25,72.65 124.85,73.375 116.6,73.6 107.6,74.1 78.475,74.25 34.9,74.4 37.75,74.4 73.275,74.425 86.25,75 102.125,75.1 13.8,75.525 1.75,75.95 62.675,76.025 8.95,76.2 68.725,76.225 48.225,76.275 18.475,76.85 26.35,76.85 117.45,77.075 82.075,77.125 28.7,77.225 39.25,77.25 112.425,77.275 84.775,77.45 76.475,77.675 72.9,77.85 93.225,78.4 114.325,78.475 34.2,78.6 21.85,78.65 105.45,78.65 12.575,78.675 33.025,78.75 18.2,79.25 24.1,79.25 8.116,79.309 68.625,79.675 13.05,80.1 20.825,80.45 102.15,80.45 26.5,80.5 96.675,80.5 18.425,80.85 107.925,80.875 24.1,81.05 78.175,81.1 125.275,81.1 111.625,81.15 20.825,81.25 26.5,81.25 66.925,81.375 68.625,81.375 70.325,81.375 92.775,81.4 88.025,81.475 14.1,81.55 18.425,81.575 82.5,81.825 1.45,82.05 98.65,82.1 22.55,82.2 41.65,82.3 85.4,82.375 117.325,82.4 32.626,82.804 37.05,82.925 68.625,83.075 18.5,83.65 112.025,83.875 114.025,83.875 116.025,83.875 13.8,84.475 76.75,84.525 64.75,84.725 60,84.8 37.7,84.9 93.95,85.45 57.375,85.475 62.975,85.65 87.925,85.75 36.125,85.825 90.675,85.825 50.327,85.854 112.025,85.875 116.025,85.875 79.025,85.975 20.95,86.025 81.775,86.15 72.95,86.175 85.45,86.175 46.75,86.325 34.375,86.425 44.475,86.525 112.325,87.2 114.125,87.2 115.925,87.2 112.325,88.2 114.125,88.2 115.925,88.2 111.2,88.225 22.7,88.25 77.4,88.3 39.375,88.475 40.85,88.5 110.125,88.525 52.55,88.6 61.275,88.675 104.375,88.75 110.65,88.95 7.9,89 43.65,89.025 71.525,89.075 115.975,89.25 112.075,89.325 114.075,89.325 69,89.475 111.025,89.525 48.55,89.675 28.05,89.775 64.6,89.825 84.25,89.975 86.65,89.975 55.025,90.025 80.325,90.075 89.275,90.075 1.825,90.2 91.8,90.225 72.725,90.25 111.2,90.25 58.775,90.375 70.2,90.525 51.225,90.6 67.675,90.7 111.2,90.95 115.975,91.25 112.075,91.325 114.075,91.325 111.2,91.575 108.225,91.675 107.525,91.95 111.225,92.3 108.35,92.575 113.725,92.575 114.35,92.575 111.85,92.65 112.525,92.8 113.125,92.8 114.925,92.8 115.525,92.8 116.15,92.8 116.775,92.8 108.35,93.225 102,93.85 106,93.85 108.175,93.925 108.2,94.575 108.675,95.075 11.025,95.15 109.175,95.475 115.425,95.6 109.8,95.625 110.4,95.625 111,95.625 111.725,95.625 112.325,95.625 112.925,95.625 113.525,95.625 114.125,95.625 114.725,95.625 116.125,95.625 116.775,95.625 102.3,95.85 106,95.85 108,95.85 39.6,95.925 32.85,95.95 104,95.975
  other v2: 90.744,30.525 71.895,32.07 85.94,37.6 87.54,37.6 63.3,42.05
  other v3: 41.3,18.075 46.775,18.126 41.1,20.025 37,22 38,22 39,22 31.725,22.425 37,23 39,23 43.8,23.026 31.725,23.075 43.8,23.725 29.3,23.9 29.875,23.9 30.55,23.9 31.05,23.9 37,24 31.85,24.25 45.7,24.675 46.325,24.675 44.3,24.7 44.95,24.7 35.375,25.025 42.05,25.85 35.75,27.75 37.525,28.325 38.95,28.325 39.675,28.325
  other v4: 67.525,33.175 66.975,35.125 33.975,87.35 31.975,87.75 33.975,88.55 31.575,89.35
GNDDetect: R74.2 U12.K13 | length 5.5
  Top Layer w0.1: U12.K13@112.675,46.6 113,46.275 114.25,46.275 115.05,45.475 115.05,44.825 115.5,44.375 R74.2@116.85,44.375
HSE_IN: C98.2 U14.T3 X4.3 | length 6.6
  Top Layer w0.075: 65.175,31.075 65.561,31.075 67.221,32.735 67.396,32.735 68.16,32.735 68.329,32.904 68.729,32.904 U14.T3@68.975,33.15
  Top Layer w0.1: X4.3@63.2,31.075 C98.2@64.375,31.075 65.175,31.075
HSE_OUT: C103.1 U14.U2 X4.1 | length 10.6
  Top Layer w0.075: 65.175,29.875 65.45,30.15 65.45,30.725 67.291,32.566 68.23,32.566 68.309,32.645 68.47,32.645 U14.U2@68.475,32.65
  Top Layer w0.1: X4.1@61.9,30.075 C103.1@61.9,29 61.928,28.972 61.928,28.629 62.256,28.3 64.125,28.3 64.6,28.775 64.6,29.3 65.175,29.875
I2C1_SCL: CN8.28 R11.1 R62.1 U14.A6 U21.26 | length 150.9
  Top Layer w0.075: U14.A6@70.475,40.65 70.475,43.125
  Top Layer w0.1: v1(70.05,44.875) 70.05,43.725 70.475,43.3 70.475,43.125 ; R11.1@71,87.25 71.65,87.25 74.64,90.24 CN8.28@74.64,92.23 ; v2(96.45,47.675) R62.1@96.45,48.25 ; v1(98.325,22.95) U21.26@99.2,22.95
  Signal Layer 2 w0.1: v1(70.05,44.875) 71.4,46.225 72.6,46.225 73.8,47.425 78.217,47.425 79.217,48.425 80.659,48.425 80.734,48.35 95.775,48.35 v2(96.45,47.675) 96.525,47.675 97.05,47.15 97.05,46.75 102.95,40.85 v1(102.95,39.35) ; v1(75.875,72.625) 98.508,72.625 99.658,71.475 v1(102.95,71.475)
  Bottom Layer w0.1: CN8.28@74.64,92.23 75.875,90.995 v1(75.875,72.625) ; v1(98.325,22.95) 103.025,27.65 103.051,27.65 103.3,27.899 103.3,28.125 103.65,28.475 103.65,37.017 102.95,37.717 v1(102.95,39.35) 102.95,43.2 103.229,43.479 103.229,71.196 v1(102.95,71.475)
I2C1_SDA: CN8.27 R10.1 R63.1 U14.B9 U21.27 | length 159.3
  Top Layer w0.075: U14.B9@71.975,40.15 71.964,40.161 71.964,40.311 71.728,40.547 71.728,41.743 72.2,42.215 72.2,43.125
  Top Layer w0.1: R10.1@69.925,87.25 69.925,87.7 70.175,87.95 71.75,87.95 73.375,89.575 73.375,93.505 CN8.27@74.64,94.77 ; v1(71.575,44.875) 72.2,44.25 72.2,43.125 ; v1(96.575,46.95) 97.525,47.9 R63.1@97.525,48.25 ; v1(97.55,22.8) 97.9,22.45 U21.27@99.2,22.45
  Signal Layer 2 w0.1: v1(71.575,44.875) 73.925,47.225 78.3,47.225 79.3,48.225 80.576,48.225 80.651,48.15 95.367,48.15 96.567,46.95 v1(96.575,46.95) 96.575,46.942 102.375,41.142 v1(102.375,38.975) ; v1(74.65,72.125) 98.725,72.125 99.875,70.975 v1(102.375,70.975)
  Bottom Layer w0.1: v1@74.64,72.125 74.64,90.075 73.375,91.34 73.375,93.505 CN8.27@74.64,94.77 ; v1(97.55,22.8) 97.574,22.8 98.149,23.375 98.225,23.375 102.44,27.59 102.44,29.825 102.55,29.935 102.55,30.726 103.15,31.326 103.15,36.625 102.375,37.4 v1(102.375,38.975) 102.289,39.061 102.289,39.245 102.275,39.259 102.275,70.753 102.375,70.853 v1(102.375,70.975)
I2C4_SCL: R75.1 U14.A9 U19.13 | length 72.2
  Top Layer w0.075: U14.A9@71.975,40.65 71.975,41.625 72.425,42.075 72.425,43.125
  Top Layer w0.1: v1(38,44.375) R75.1@38,45.05 ; 72.425,43.125 72.425,43.925 72.85,44.35 v1(72.85,44.8)
  Top Layer w0.12: v1@38,44.35 38,44.2 38,42.25 39.375,40.875 39.375,38.05 38.225,36.9 38.225,34.25 39.875,32.6 41.375,32.6 42.975,31 42.975,25.925 42.295,25.245 40.934,25.245 40.53,24.841 40.53,23.955 40.375,23.8 U19.13@39.9,23.8
  Signal Layer 2 w0.09: 64.811,41.9 65.011,41.7 70.875,41.7 72.3,43.125
  Signal Layer 2 w0.1: v1@38,44.4 38,45.225 38.425,45.65 41.737,45.65 44.437,42.95 54.275,42.95 55.675,41.55 61.175,41.55 61.775,40.95 62.85,40.95 63.8,41.9 64.811,41.9 ; 72.3,43.125 72.85,43.675 v1(72.85,44.8)
I2C4_SDA: R71.1 U14.A15 U19.12 | length 70
  Top Layer w0.075: U14.A15@74.975,40.65 74.975,41.925 75.15,42.1 75.15,42.568 v1(75.143,42.575)
  Top Layer w0.1: v1(39.1,44.375) R71.1@39.1,45.05
  Top Layer w0.12: v1(39.1,44.375) 39.1,44.225 39.1,41.775 39.595,41.28 39.595,37.92 38.445,36.77 38.445,34.341 39.966,32.82 41.466,32.82 43.2,31.086 43.2,25.839 42.386,25.025 41.025,25.025 40.75,24.75 40.75,23.825 40.332,23.407 39.907,23.407 U19.12@39.9,23.4
  Signal Layer 2 w0.09: 65.175,41.5 71.163,41.5 72.238,42.575 v1(75.143,42.575)
  Signal Layer 2 w0.1: v1(39.1,44.375) 39.1,45.2 39.35,45.45 41.654,45.45 44.354,42.75 50.919,42.75 51.89,41.779 53.259,41.779 53.877,42.397 54.503,42.397 55.575,41.325 61.117,41.325 61.717,40.725 62.908,40.725 63.883,41.7 64.575,41.7 64.775,41.5 65.175,41.5
I2C5_SCL_1V8: R169.1 R171.1 TR2.2 U2.F5 | length 24.7
  Signal Layer 1 w0.1: v1(29.675,87) 29.683,87 30.883,88.2 31.898,88.2 31.948,88.15 v4(31.975,88.15)
  Signal Layer 2 w0.1: v1(15.675,89.25) 15.675,87.95 16.65,86.975 23.775,86.975 v1(25.5,88.7) 27.2,87 v1(29.675,87)
  Bottom Layer w0.1: R169.1@14.7,92.15 14.825,92.025 14.825,91.125 TR2.2@15.2,90.75 TR2.2@15.2,90.125 ; v1(15.675,89.25) 15.2,89.725 TR2.2@15.2,90.125 ; R171.1@16.625,90 16.5,90.125 TR2.2@15.2,90.125
I2C5_SDA_1V8: R168.1 R170.1 TR1.2 U2.G6 | length 15.5
  Top Layer w0.1: v2(30.975,87.75) U2.G6@31.575,87.75
  Signal Layer 2 w0.1: v1(22.2,89.425) 22.725,88.9 24.925,88.9 25.15,89.125 26.875,89.125 27.25,88.75 27.25,88.025 27.675,87.6 29.625,87.6 29.775,87.75 v2(30.975,87.75)
  Bottom Layer w0.1: R168.1@19.45,92.15 19.575,92.025 19.575,91.125 TR1.2@19.95,90.75 19.95,90.25 21.15,90.25 21.496,89.904 21.721,89.904 v1(22.2,89.425)
ISENSE_MEAS: TP53.1 U20.4 U21.14 | length 13.6
  Top Layer w0.1: U21.14@103.075,24.95 103.75,25.625 108.6,25.625 109.95,26.975 112.375,26.975 ; TP53.1@112.375,28.325 112.375,26.975 ; U20.4@113.4,25.325 113.4,25.95 112.375,26.975
LCD_B2: CN16.23 U14.D6 | length 26.4
  Top Layer w0.09: v2@70.025,39.15 U14.D6@70.475,39.15
  Bottom Layer w0.09: v2(69.925,39.15) 69.925,39.231 70.025,39.331 70.025,43.125
  Bottom Layer w0.1: CN16.23@65.525,63.15 CN16.23@65.525,63.1 65.525,61.293 65.45,61.218 65.45,49.225 69.225,45.45 69.225,44.975 70.025,44.175 70.025,43.125
LCD_B3: CN16.24 U14.D11 | length 34.4
  Top Layer w0.09: U14.D11@72.975,39.15 72.988,39.163 73.438,39.163 v2@73.45,39.175
  Top Layer w0.1: v1(73.575,45.6) v1(73.575,54.15)
  Signal Layer 2 w0.219: v1(64.7,54.15) 64.75,54.1 73.525,54.1 v1(73.575,54.15)
  Bottom Layer w0.09: v2(73.525,39.225) 73.525,39.975 74.725,41.175 74.725,43.125
  Bottom Layer w0.1: v1(64.7,54.15) 65.025,54.475 CN16.24@65.025,63.1 ; v1(73.575,45.6) 74.725,44.45 74.725,43.125
LCD_B4: CN16.25 U14.B8 | length 31.2
  Top Layer w0.075: 71.3,43.125 71.3,42.975 71.39,42.885 71.39,40.272 71.475,40.187 U14.B8@71.475,40.15
  Top Layer w0.1: v1(71.1,53.05) 71.1,50.55 71.525,50.125 71.525,49.45 71.05,48.975 71.05,46.649 71.125,46.574 71.125,43.781 71.3,43.606 71.3,43.125
  Signal Layer 2 w0.219: v1(63.9,53.05) v1(71.1,53.05)
  Bottom Layer w0.1: v1(63.9,53.05) 63.9,57.25 64.774,58.124 64.774,61.458 64.525,61.707 CN16.25@64.525,63.1
LCD_B5: CN16.26 U14.B6 | length 31.2
  Top Layer w0.075: 70.1,43.125 70.1,42.925 70.228,42.797 70.228,40.548 70.45,40.326 70.45,40.175 U14.B6@70.475,40.15
  Top Layer w0.1: v1(69.875,47.775) 69.325,47.225 69.325,45.875 69.625,45.575 69.625,43.85 70.1,43.375 70.1,43.125
  Signal Layer 2 w0.219: v1(63.1,47.775) v1(69.875,47.775)
  Bottom Layer w0.1: v1(63.1,47.775) 63.1,51.5 63.1,57.378 64.453,58.731 64.453,61.178 64.025,61.606 CN16.26@64.025,63.1
LCD_B6: CN16.27 U14.C1 | length 25.7
  Top Layer w0.075: 65.975,43.125 66.31,42.79 66.31,40.69 67.35,39.65 U14.C1@67.975,39.65
  Top Layer w0.1: v1(63.925,60.75) 63.925,54.15 64.65,53.425 64.65,44.45 65.975,43.125
  Bottom Layer w0.1: CN16.27@63.525,63.1 63.525,61.15 v1(63.925,60.75)
LCD_B7: CN16.28 U14.B11 | length 38.2
  Top Layer w0.075: U14.B11@72.975,40.15 72.975,40.187 72.89,40.272 72.89,41.415 73.25,41.775 73.25,43.125
  Top Layer w0.1: 73.25,43.125 73.25,43.583 73.925,44.258 73.925,44.703 74.775,45.553 74.775,48.924 74.7,48.999 74.7,49.351 74.775,49.426 v1(74.775,53.6)
  Signal Layer 2 w0.219: v1(61.5,53.6) v1(74.775,53.6)
  Bottom Layer w0.1: v1(61.5,53.6) 61.5,54.225 62.8,55.525 62.8,58.03 63.575,58.805 63.575,60.271 63.025,60.821 CN16.28@63.025,63.1
LCD_BL: R57.1 U14.A4 | length 32.4
  Top Layer w0.075: 68.325,43.125 68.325,42.5 69.475,41.35 U14.A4@69.475,40.65
  Top Layer w0.1: 68.325,43.125 68.325,49.924 68.275,49.974 68.275,54.575 v1@68.325,54.625 ; v1(84.975,55.45) R57.1@85.775,55.45
  Signal Layer 2 w0.1: v1(68.253,54.628) 73.622,54.628 73.625,54.625 74.025,55.025 84.55,55.025 v1(84.975,55.45)
LCD_BL_A: C54.2 CN16.2 R60.2 | length 17.8
  Top Layer w0.3: v1(82.3,53.1) 83.25,53.1 83.475,53.325 C54.2@83.475,53.9 R60.2@84.5,53.9
  Bottom Layer w0.3: CN16.2@76.025,63.1 76.025,59.475 77.206,58.294 80.9,58.294 82.175,57.019 82.175,55.6 81.95,55.375 81.95,53.518 82.3,53.168 v1(82.3,53.1)
LCD_BL_K: CN16.1 R49.2 U9.4 | length 17.1
  Top Layer w0.3: v1(83.1,55.475) 83.1,57.375 R49.2@82.95,57.525 82.95,57.65 83.575,58.275 U9.4@85.075,58.275
  Bottom Layer w0.3: CN16.1@76.525,63.1 76.525,59.878 77.515,58.888 81.137,58.888 83.1,56.925 v1(83.1,55.475)
LCD_CLK: CN16.30 TP41.1 U14.C9 | length 41.2
  Top Layer w0.075: 71.559,43.125 71.559,40.441 71.725,40.275 71.725,39.9 U14.C9@71.975,39.65
  Top Layer w0.1: TP41.1@62.975,66.125 63.15,65.95 v1(63.15,65.1) ; 71.559,43.125 71.559,43.291 71.521,43.329 71.521,43.971 v1(71.565,44.015)
  Signal Layer 2 w0.219: v1(59.9,44.015) 60.81,44.925 66.751,44.925 67.651,44.025 71.555,44.025 v1(71.565,44.015)
  Bottom Layer w0.1: v1(59.9,44.015) 59.9,51.5 61.025,52.625 61.025,58.734 62.69,60.399 62.69,61.602 62.025,62.267 CN16.30@62.025,63.1 62.025,64.275 62.799,65.049 63.099,65.049 v1(63.15,65.1)
LCD_DE: CN16.34 TP40.1 U14.C12 | length 50.8
  Top Layer w0.075: 73.45,43.125 73.45,41.725 73.059,41.334 73.059,40.441 73.221,40.279 73.221,39.904 U14.C12@73.475,39.65
  Top Layer w0.1: TP40.1@58.45,66.025 59.3,66.025 v1(59.65,65.675) ; 73.45,43.125 73.45,43.5 74.125,44.175 74.125,44.621 75.125,45.621 v1(75.125,49.175)
  Signal Layer 2 w0.1: v1(56.7,49.175) 56.822,49.175 56.922,49.075 74.841,49.075 74.855,49.089 75.039,49.089 v1(75.125,49.175)
  Bottom Layer w0.1: v1(56.7,49.175) 56.7,55.6 61.9,60.8 61.9,61.275 61.45,61.725 60.45,61.725 60.025,62.15 CN16.34@60.025,63.1 60.106,63.181 60.106,63.681 60.325,63.9 60.325,65 v1(59.65,65.675)
LCD_DISP: CN16.31 R59.2 U14.AA20 | length 57.8
  Top Layer w0.09: v1(61.325,64.25) R59.2@61.325,64.875 ; U14.AA20@77.474,30.65 77.475,30.046 77.475,29.49 77.661,29.304 77.661,28.858 v6(77.675,28.844)
  Signal Layer 2 w0.1: v1(58.975,52.875) 61.125,50.725 77.175,50.725 77.75,50.15 77.75,48.834 77.525,48.609 v1(77.525,48.55)
  Signal Layer 3 w0.09: v1(77.525,48.55) 77.525,48.426 77.671,48.279 77.671,45.996 77.25,45.575 77.25,29.425 77.616,29.059 77.616,28.903 77.638,28.881 v6(77.675,28.844)
  Bottom Layer w0.09: v1(58.975,52.875) 59.467,52.875 60.7,54.108 60.7,58.7 62.495,60.495 62.495,61.522 61.525,62.492 CN16.31@61.525,63.1 61.525,63.967 61.325,64.167 v1(61.325,64.25)
LCD_G2: CN16.15 U14.A12 | length 30.5
  Top Layer w0.075: U14.A12@73.475,40.65 73.475,40.775 73.795,41.095 73.795,41.8 73.65,41.945 73.65,43.125
  Top Layer w0.1: 73.65,43.125 73.65,43.408 74.325,44.083 74.325,44.538 75.5,45.713 75.5,47.497 75.55,47.547 75.55,49.33 75.5,49.38 75.5,61.975 v1(75.475,62)
  Signal Layer 2 w0.219: v1(70.025,64.375) 70.094,64.375 70.319,64.6 72.875,64.6 v1(75.475,62)
  Bottom Layer w0.1: CN16.15@69.525,63.1 69.525,63.928 69.972,64.375 v1(70.025,64.375)
LCD_G3: CN16.16 U14.A13 | length 30.2
  Top Layer w0.075: U14.A13@73.975,40.65 74.135,40.81 74.135,41.965 74.075,42.025 74.075,43.125
  Top Layer w0.1: v1(70.55,61.025) 70.55,59.576 70.937,59.189 70.937,53.587 70.675,53.325 70.675,50.1 v1(71.1,49.675) ; 74.075,43.125 74.075,43.25 74.25,43.425 74.725,43.9 74.725,44.372 75.9,45.547 75.9,46.691 76.25,47.041 v1(76.25,49.675)
  Signal Layer 2 w0.219: v1(71.1,49.675) v1(76.25,49.675)
  Bottom Layer w0.1: CN16.16@69.025,63.1 69.025,62.434 69.2,62.259 70.115,62.259 70.55,61.825 v1(70.55,61.025)
LCD_G4: CN16.17 U14.C8 | length 26.1
  Top Layer w0.075: 71.1,43.125 71.1,42.35 71.221,42.229 71.221,40.752 71.221,40.048 71.221,39.904 U14.C8@71.475,39.65
  Top Layer w0.1: v1(70.45,57.475) 70.45,57.416 70.3,57.266 70.3,49.675 70.853,49.122 70.853,49.06 70.85,49.058 70.85,46.566 70.925,46.491 70.925,43.699 71.1,43.524 71.1,43.125
  Bottom Layer w0.1: CN16.17@68.525,63.1 68.525,62.15 68.75,61.925 69.776,61.925 70.1,61.601 70.1,60.807 70.55,60.357 70.55,59.992 69.675,59.117 69.675,58.25 v1(70.45,57.475)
